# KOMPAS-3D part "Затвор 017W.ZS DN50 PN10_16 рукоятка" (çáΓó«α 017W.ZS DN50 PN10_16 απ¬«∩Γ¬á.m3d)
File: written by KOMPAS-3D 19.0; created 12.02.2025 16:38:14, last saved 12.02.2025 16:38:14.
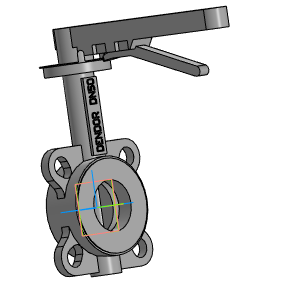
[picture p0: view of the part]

Document properties: Автор: Евгений; Полное имя файла: Затвор 017W.ZS DN50 PN10_16 рукоятка.a3d

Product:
- Part/product: Затвор 017W.ZS DN50 PN10_16 рукоятка
    Масса: 4.37313

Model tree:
1. Операция без истории:1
